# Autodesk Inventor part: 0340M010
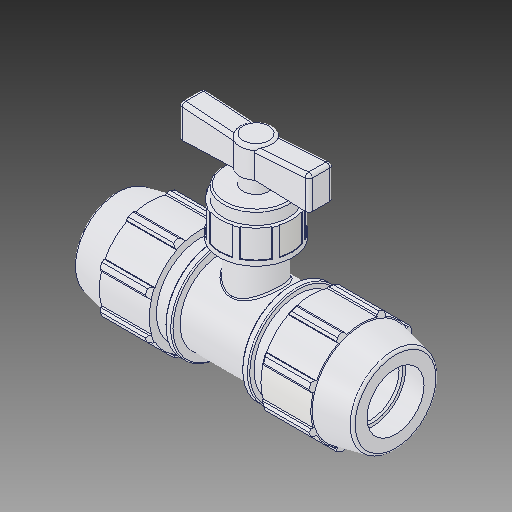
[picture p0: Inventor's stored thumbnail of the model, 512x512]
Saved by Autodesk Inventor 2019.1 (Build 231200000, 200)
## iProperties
Created: 2017-02
Part Number: 0340M010
Material: PVC-Piping
Description: PLASSON COMPRESSION STOPTAP 1'' - 1''
Document SubType Name: Modeling
Designer: KIM
Mass: 92.6774 g
Surface Area: 199.44 cm^2
Volume: 66.1981 cm^3
Density: 1.4 g/cm^3
Appearance: PTFE
Author: KIM
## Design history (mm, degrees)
derived "0340M0.ipt"
feature "Solid1::0340M0.ipt"
tag "TaggingFeature1"
body "Solid1"
other parameters: "d1" = 163.068, "d2" = 33.3, "d4" = 13.589, "d5" = 19.56816, "d7" = 64.008, "d8" = 48.006, "d9" = 40.767, "d11" = 4.0767, "d12" = 51.2064, "d13" = 120 deg, "d14" = 49.95, "d15" = 12 deg, "d16" = 57.6072, "d18" = 1.665, "d19" = 35 deg, "d20" = 17.5 deg, "d21" = 59.52744, "d23" = 0, "d25" = 360 deg, "d27" = 1.28016, "d33" = 0.666, "d42" = 29.35224, "d43" = 1.92024, "d46" = 0.999, "d49" = 70.104, "d50" = 26.64, "d51" = 94.996, "d53" = 18.9992, "d54" = 18.9992, "d57" = 17.09928, "d60" = 42.7482, "d61" = 28.4988, "d62" = 18.9992, "d63" = 61.7474, "d64" = 15.19936, "d65" = 37.9984, "d66" = 7.59968, "d69" = 12.82446, "d70" = 6.41223, "d71" = 41.89324, "d72" = 41.4, "d74" = 0, "d75" = 16.14932, "d76" = 92, "d77" = 92, "d80" = 360 deg, "d82" = 0.37998, "d85" = 37.9984, "d86" = 6 deg, "d87" = 94 deg, "d88" = 14.2494, "d89" = 0, "d90" = 2, "d91" = 2, "d92" = 0.94996, "d93" = 0.94996, "d_" = 33.3, "E_" = 64.008, "H_" = 163.068, "l_" = 70.104, "A_" = 94.996, "d67" = 92, "d78" = 42.7482
